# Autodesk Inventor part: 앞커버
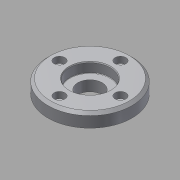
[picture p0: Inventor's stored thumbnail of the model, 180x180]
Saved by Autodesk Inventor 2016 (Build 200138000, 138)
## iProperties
Created: 2015-09
Part Number: 앞커버
Material: 알루미늄 6061
Document SubType Name: Modeling
Designer: mduedu
Density: 1 g/cm^3
Appearance: 알루미늄 - 평지
Author: mduedu
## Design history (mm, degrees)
sketch "스케치1"
  geometry: L1 (0, 7.5)-(0, -7.5); L2 (0, 7.5)-(31, 7.5); L3 (31, 7.5)-(31, -2.5); L4 (31, -2.5)-(17.5, -2.5); L5 (17.5, -2.5)-(17.5, -7.5); L6 (17.5, -7.5)-(0, -7.5); 2 further points
  constraints: 12 end point, 2 parallel, 2 perpendicular, 1 coincident, 1 horizontal, 1 midpoint, 1 vertical
  dimensions: "d0" = 15 distance of L1.start L1.end; "d1" = 62 diameter of L3 L1; "d2" = 35 diameter of L5 L1; "d3" = 10 distance of L2.end L3.end
revolve "회전1" sketch "스케치1" stored, may be unused: angle "d4" = 90 deg
hole "구멍1" diameter "d7" = 30; stored, may be unused: countersink angle "d11" = 90 deg, drill point angle "d13" = 0 deg; dims "d5" = 10, "d6" = 10, "d8" = 6, "d9" = 4, "d10" = 2, "d12" = 7.3
hole "구멍2" diameter "d16" = 18; stored, may be unused: countersink angle "d20" = 90 deg, drill point angle "d22" = 0 deg; dims "d14" = 10, "d15" = 10, "d17" = 6, "d18" = 4, "d19" = 2, "d21" = 7.3
chamfer "모따기1" distance "d23" = 2; stored, may be unused: second distance "d24" = 2, angle "d25" = 45 deg
chamfer "모따기2" distance "d26" = 0.7; stored, may be unused: second distance "d27" = 2, angle "d28" = 30 deg
fillet "모깎기1" dims "d29" = 0.3
sketch "스케치2" dims "d30" = 45
  geometry: 6 further points
  constraints: 2 vertical alignment, 1 coincident, 7 other
  dimensions: "d34" = 360 deg dimension on point (0, 0) point (0, 22.5) (derived)
sketch "스케치3"
  geometry: 4 further points
hole "구멍3" sketch "스케치3" at (0, 22.5), (-22.5, 0), (22.5, 0), (0, -22.5) diameter "d36" = 4.5; stored, may be unused: countersink angle "d40" = 90 deg, drill point angle "d42" = 0 deg; dims "d37" = 6, "d38" = 8, "d39" = 4.6, "d41" = 8
node "솔리드1"
